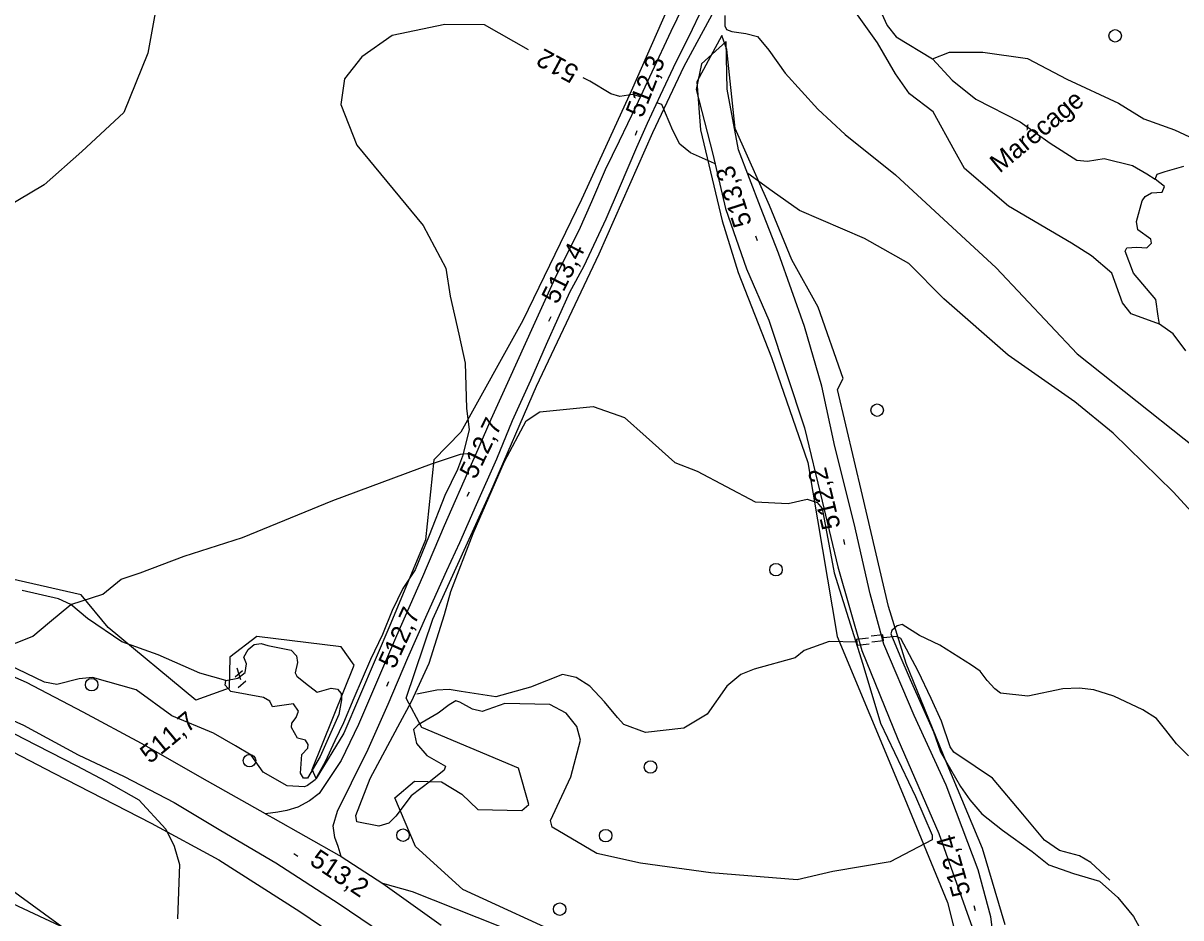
# Model space of a CAD drawing. Extents: x 347059 to 352153, y 6073752 to 6078601.
# Drawn here: x 349136.4 to 349414.6, y 6075948.3 to 6076163.4 of the extents above; entities that cross this region are included whole.
import ezdxf

# ---------------------------------------------------------------- set-up
doc = ezdxf.new("R2010")
doc.units = 0
for name, color, linetype in [('Level 1', 7, 'Continuous'), ('Level 19', 7, 'Continuous'), ('Level 2', 7, 'Continuous'), ('Level 21', 7, 'Continuous'), ('Level 22', 7, 'Continuous'), ('Level 26', 7, 'Continuous'), ('Level 3', 7, 'Continuous'), ('Level 36', 7, 'Continuous'), ('Level 37', 7, 'Continuous'), ('Level 4', 7, 'Continuous'), ('Level 44', 7, 'Continuous'), ('Level 7', 7, 'Continuous')]:
    doc.layers.add(name, color=color, linetype=linetype)

msp = doc.modelspace()

# ---------------------------------------------------------------- linework, layer by layer
at = {"layer": 'Level 1'}
for points in [[(349305.02, 6076165.23), (349305, 6076162.73), (349305.41, 6076161.87), (349306.72, 6076161.39), (349310.05, 6076160.92), (349312.85, 6076160.17)], [(349312.85, 6076160.17), (349315.56, 6076156.93), (349319.52, 6076151.42), (349327.38, 6076142.73), (349333.9, 6076136.65), (349346.01, 6076126.93), (349370.23, 6076104.59), (349389.67, 6076083.93), (349429.81, 6076052.02), (349436.05, 6076046.93)]]:
    msp.add_lwpolyline(points, dxfattribs=at)
at = {"layer": 'Level 19'}
for points in [[(349370.57, 6075935.79), (349368.94, 6075948.55), (349365.87, 6075959.81), (349358.21, 6075980.17), (349350.54, 6075996.92), (349343.25, 6076014.13), (349339.93, 6076026.23), (349336.06, 6076043.12), (349331.44, 6076061.63), (349328.34, 6076076.15), (349324.16, 6076090.51), (349317.9, 6076108.1), (349313.59, 6076119.2), (349308.28, 6076132.95), (349305.59, 6076147.53), (349305.34, 6076159.03), (349299.42, 6076153.66), (349298.11, 6076147.47), (349302.1, 6076131.88), (349305.17, 6076118.85), (349310.23, 6076104.32), (349315.58, 6076091.97), (349324.12, 6076066.08), (349328.41, 6076048.5), (349332.13, 6076032.68), (349337.93, 6076012.58), (349346.56, 6075991.24), (349356.47, 6075968.54), (349364.43, 6075946.03)], [(349255.95, 6075944.25), (349229.96, 6075954.53), (349222.77, 6075956.58)]]:
    msp.add_lwpolyline(points, dxfattribs=at)
at = {"layer": 'Level 2'}
for points in [[(349257.8, 6076157.01), (349247.23, 6076163.04), (349237.72, 6076163.08), (349225.01, 6076160.46), (349217.73, 6076155.31), (349213.56, 6076150.04), (349212.74, 6076143.81), (349216.52, 6076134.06), (349232.46, 6076114.78), (349237.91, 6076104.47), (349239.01, 6076097.74), (349241.05, 6076088.64), (349242.61, 6076081.62), (349242.94, 6076070.87), (349243.53, 6076065.66), (349241.96, 6076059.33)], [(349284.66, 6076145.66), (349282.89, 6076146.29), (349279.8, 6076145.75), (349277.63, 6076146.43), (349272.56, 6076149.43), (349270.93, 6076150.25)], [(349302.62, 6076129.67), (349302.53, 6076129.7), (349296.77, 6076132.19), (349294.22, 6076134.34), (349292.47, 6076137.61), (349289.84, 6076143.82), (349288.65, 6076144.24)], [(349429.29, 6076031.19), (349419.03, 6076043.95), (349412.75, 6076050.7), (349398.36, 6076064.84), (349389.11, 6076072.35), (349373.12, 6076083.61), (349357.65, 6076097.15), (349349.2, 6076105.6), (349338.6, 6076111.67), (349322.92, 6076118.37), (349316.41, 6076123.01), (349310.56, 6076127.22), (349310.48, 6076127.24)], [(349257.22, 6076067.83), (349260.53, 6076069.98), (349273.36, 6076071.2), (349280.92, 6076068.63), (349286.07, 6076063.91), (349292.98, 6076057.79), (349298.36, 6076055.67), (349312.3, 6076048.35), (349320.22, 6076047.88), (349324.76, 6076048.94), (349327.23, 6076048.14), (349328.41, 6076046.73), (349331.3, 6076031.27), (349338.2, 6076009.31), (349342.44, 6075995.12), (349350.8, 6075977.44), (349354.84, 6075968.18), (349354.82, 6075967.03), (349344.77, 6075961.76), (349330.92, 6075959.41), (349322.4, 6075957.44), (349301.61, 6075959.09), (349284.75, 6075961.44), (349274.21, 6075963.79), (349263.54, 6075970.09), (349263.11, 6075971.68), (349268.02, 6075982.21), (349270.31, 6075991.02), (349269.42, 6075994.33), (349266.88, 6075997.47), (349262.97, 6075999.63), (349252.16, 6075999.87), (349246.68, 6075997.87), (349244.38, 6075998.47)], [(349244.38, 6075998.47), (349241.3, 6076000.18), (349240.38, 6076000.47), (349238.77, 6075999.51), (349236.09, 6075997.5), (349231.27, 6075994.7), (349230.19, 6075993.58), (349230.86, 6075990.24), (349233.35, 6075987.35), (349237.87, 6075984.73), (349237.53, 6075983.78), (349234.3, 6075981.16), (349229.62, 6075977.66), (349225.97, 6075972.75), (349224.26, 6075971.1), (349221.86, 6075970.38), (349216.58, 6075971.39), (349216.35, 6075972.93), (349219.79, 6075981.79), (349226.43, 6075994.2), (349229.72, 6076000.35), (349233.97, 6076009.51), (349237.59, 6076021.21), (349239.12, 6076026.77), (349244.55, 6076040.73), (349252.01, 6076058.02), (349257.22, 6076067.83)], [(349241.96, 6076059.33), (349240.77, 6076056.11), (349237.69, 6076049.88), (349233.97, 6076040.23), (349230.54, 6076032), (349227.63, 6076027.5), (349225.07, 6076022.23), (349222.69, 6076016.44), (349219.84, 6076010.4), (349219.84, 6076010.4), (349215.86, 6076001.1), (349213.39, 6075995.2), (349211.29, 6075990.83), (349208.91, 6075985.84), (349206.51, 6075981.5), (349204.71, 6075980.15), (349203.95, 6075979.8), (349199.78, 6075980.01), (349194.06, 6075983.36), (349191.2, 6075987.42), (349187.43, 6075989.69), (349182.08, 6075992.67), (349172.1, 6075996.9), (349163.53, 6076003.12), (349153.06, 6076006.11), (349149.83, 6076005.75), (349144.42, 6076004.4), (349141.52, 6076004.99), (349130.57, 6076010.2)], [(349351.79, 6076016.17), (349347.64, 6076018.86), (349346.45, 6076018.54), (349345.17, 6076017.37), (349344.88, 6076016.6), (349347.04, 6076011.36), (349349.52, 6076005.58), (349355.17, 6075993), (349356.8, 6075988.25), (349361.64, 6075979.9), (349363.86, 6075976.69), (349366.78, 6075973.27), (349371.76, 6075969.41), (349378.86, 6075964.24), (349382.89, 6075961.06), (349388.77, 6075959), (349395.03, 6075957.12), (349399.42, 6075953.18), (349403.25, 6075948.64), (349406.31, 6075942.95)], [(349416.44, 6075987.22), (349413.54, 6075990.14), (349410.97, 6075993.45), (349408.71, 6075996.23), (349405.44, 6075998.31), (349398.45, 6076001.58), (349393.68, 6076003.09), (349390.17, 6076003.53), (349386.25, 6076003.36), (349377.82, 6076001.62), (349371.23, 6076002.31), (349369.88, 6076003.32), (349368.05, 6076005.4), (349366.38, 6076007.6), (349364.28, 6076009.06), (349356.71, 6076013.84), (349351.79, 6076016.17)], [(349122.22, 6075998.85), (349136.41, 6075991.38), (349149.3, 6075984.85), (349156.21, 6075981.15), (349164.17, 6075976.66), (349170.69, 6075969.64), (349172.66, 6075965.57), (349173.93, 6075961.15), (349173.47, 6075948.09)]]:
    msp.add_lwpolyline(points, dxfattribs=at)
at = {"layer": 'Level 21'}
for points in [[(349296.43, 6076170.52), (349292.02, 6076161.37), (349287.43, 6076151.64), (349283.59, 6076143.35), (349279.63, 6076135.03), (349276.25, 6076128.18), (349272.92, 6076120.47), (349269.91, 6076113.55), (349264.51, 6076102.93), (349258.91, 6076090.56), (349253.19, 6076077.79), (349248.78, 6076068.13), (349245.05, 6076059.59), (349244.05, 6076057.31), (349237.53, 6076042.51), (349232.34, 6076030.26), (349226.12, 6076016.1), (349221.06, 6076004.32), (349216.94, 6075994.75), (349212.82, 6075986.09), (349207.47, 6075978.19), (349205.22, 6075976.47), (349202.37, 6075974.93), (349199.72, 6075974.14), (349197.59, 6075973.72), (349194.58, 6075973.32)], [(349212.81, 6075963.01), (349212.11, 6075965.47), (349211.28, 6075967.63), (349210.88, 6075970.45), (349211.94, 6075973.95), (349215.27, 6075980.77), (349219.26, 6075988.87), (349224.07, 6075999.69), (349228.78, 6076010.8), (349233.44, 6076021.34), (349238.17, 6076031.8), (349241.29, 6076038.51), (349245.29, 6076047.68), (349250.23, 6076058.69), (349253.99, 6076067.88), (349258.4, 6076077.54), (349262.15, 6076086.19), (349267.76, 6076098.72), (349271.17, 6076105.08), (349276.47, 6076116.37), (349279.65, 6076123.8), (349283.87, 6076133.61), (349286.41, 6076139.4), (349289.53, 6076146.12), (349293.3, 6076154.13), (349296.4, 6076160.24), (349299.71, 6076167.19)], [(349194.58, 6075973.32), (349180.66, 6075981.15), (349164.82, 6075990.24), (349150.8, 6075997.78), (349137.19, 6076004.9), (349127.02, 6076009.26)], [(349126.47, 6075999.15), (349136.46, 6075994.64), (349149.61, 6075987.51), (349160.65, 6075982.3), (349172.62, 6075976.05), (349183.84, 6075969.26), (349197.1, 6075961.55), (349212.34, 6075951.65), (349225.19, 6075942.91)], [(349194.58, 6075973.32), (349196.36, 6075972.32), (349212.21, 6075963.39), (349212.81, 6075963.01), (349222.77, 6075956.58), (349236.8, 6075946.51)]]:
    msp.add_lwpolyline(points, dxfattribs=at)
at = {"layer": 'Level 22'}
msp.add_lwpolyline([(349124.39, 6076010.3), (349124.98, 6076013.19), (349127.47, 6076015.25), (349134.52, 6076014.37), (349138.69, 6076016.04), (349142.69, 6076019.36), (349147.83, 6076023.6), (349155.52, 6076026.09), (349159.88, 6076029.71), (349164.45, 6076031.26), (349175.07, 6076035.29), (349189.1, 6076039.75), (349210.76, 6076048.6), (349234.54, 6076057.42), (349241.48, 6076059.74), (349243.14, 6076059.92), (349245.05, 6076059.59)], dxfattribs=at)
at = {"layer": 'Level 26'}
for p, q in [((349336.63, 6076015.33), (349339.49, 6076015.65)), ((349336.63, 6076015.33), (349336.81, 6076013.87)), ((349343.01, 6076016.35), (349340.14, 6076016.03)), ((349343.17, 6076014.89), (349343.01, 6076016.35)), ((349336.81, 6076013.87), (349339.66, 6076014.21)), ((349343.17, 6076014.89), (349340.31, 6076014.59))]:
    msp.add_line(p, q, dxfattribs=at)
at = {"layer": 'Level 3'}
for p, q in [((349283.53, 6076136.44), (349283.97, 6076137.56)), ((349312.84, 6076111.04), (349312.47, 6076112.18)), ((349262.72, 6076091.79), (349263.26, 6076092.86)), ((349243.11, 6076049.67), (349243.64, 6076050.75)), ((349333.86, 6076038.1), (349333.57, 6076039.27)), ((349187.29, 6076006.24), (349189.1, 6076007.73)), ((349187.75, 6076008.37), (349188.58, 6076005.62)), ((349188.01, 6076003.72), (349189.86, 6076005.25)), ((349223.78, 6076004.04), (349224.28, 6076005.13)), ((349201.38, 6075963.77), (349202.38, 6075963.1)), ((349365.26, 6075949.99), (349364.93, 6075951.15))]:
    msp.add_line(p, q, dxfattribs=at)
at = {"layer": 'Level 36'}
for centre in [(349398.81, 6076160.37), (349341.6, 6076070.35), (349317.28, 6076032), (349152.83, 6076004.36), (349190.77, 6075986.09), (349287.13, 6075984.56), (349227.67, 6075968.16), (349276.37, 6075968.06), (349265.31, 6075950.37)]:
    msp.add_circle(centre, 1.5, dxfattribs=at)
at = {"layer": 'Level 37'}
msp.add_lwpolyline([(349105.83, 6075964.84), (349145.26, 6075946.36), (349226.4, 6075910.98), (349265.54, 6075890.33), (349312.79, 6075813.11), (349333.88, 6075779.73), (349343.28, 6075763.05)], dxfattribs=at)
at = {"layer": 'Level 4'}
for points in [[(349318.16, 6076192.02), (349322.53, 6076191.3), (349327.23, 6076189.19), (349333, 6076183.47), (349336.12, 6076178.56), (349339.38, 6076173.22), (349342.69, 6076165.83), (349344.02, 6076162.88), (349346.19, 6076160.1), (349354.89, 6076154.85), (349359.64, 6076149.7), (349365.31, 6076145.17), (349375.96, 6076139.65), (349383.19, 6076134.53), (349389.61, 6076130.46), (349392.18, 6076130.19), (349396.2, 6076130.89), (349402.96, 6076129.22), (349406.43, 6076127.14), (349408.44, 6076125.92)], [(349415.78, 6076084.61), (349412.73, 6076088.71), (349409.44, 6076091.02), (349409.17, 6076092.97), (349408.59, 6076097), (349403.2, 6076103.28), (349401.21, 6076108.55), (349401.62, 6076109.42), (349404.02, 6076109.53), (349406.43, 6076109.35), (349407.52, 6076110.48), (349407.36, 6076111.48), (349404.28, 6076113.73), (349403.97, 6076115.73), (349405.28, 6076120.66), (349406.04, 6076121.74), (349407.56, 6076122.63), (349410.09, 6076122.77), (349410.67, 6076124.16), (349408.44, 6076125.92), (349408.88, 6076127.11), (349410.83, 6076127.76), (349415.35, 6076129.03)], [(349185.11, 6076005.39), (349178.79, 6076007.11), (349168.82, 6076011.5), (349160.05, 6076014.63), (349151.83, 6076020.25), (349147.83, 6076023.6), (349144.85, 6076025.01), (349136.13, 6076026.99)], [(349397.55, 6075957.36), (349392.97, 6075961.59), (349390.27, 6075963.21), (349385.42, 6075964.51), (349381.86, 6075966.97), (349376.64, 6075973.22), (349369.34, 6075981.87), (349365.16, 6075984.71), (349360.05, 6075988.13), (349359.14, 6075989.4), (349357.04, 6075995.61), (349354.62, 6076001.03), (349351.45, 6076007.63), (349347.32, 6076015.46), (349346.22, 6076015.97), (349343.11, 6076015.64)], [(349189.4, 6076010.98), (349190.48, 6076012.85), (349191.85, 6076013.99), (349193.6, 6076014.24), (349195.2, 6076013.77), (349200.76, 6076012.69), (349202.02, 6076011.27), (349202.29, 6076009.69), (349201.77, 6076007.24), (349202.15, 6076006.43), (349204.21, 6076004.76), (349207.01, 6076002.59), (349210.42, 6076003.55), (349211.95, 6076003.24), (349212.8, 6076002.22), (349212.87, 6076000.7), (349212.26, 6075997.2), (349207.76, 6075987.08), (349204.7, 6075981.91), (349203.75, 6075981.87), (349202.99, 6075983.05), (349203.37, 6075987.56), (349204.78, 6075989.11), (349204.9, 6075989.96), (349204.18, 6075991.01), (349202.26, 6075991.51), (349200.89, 6075994.05), (349200.91, 6075995.11), (349201.97, 6075996.45), (349202.56, 6075997.99), (349201.33, 6075999.74), (349196.3, 6075999.01), (349195.61, 6076000.39), (349194.09, 6076001.3), (349186.3, 6076002.7), (349184.88, 6076004.23), (349185.11, 6076005.39), (349187.96, 6076005.95), (349189.72, 6076007.27), (349190.07, 6076009.36), (349189.4, 6076010.98)], [(349336.69, 6076014.58), (349330.05, 6076014.77), (349324.06, 6076012.57), (349321.93, 6076010.8), (349312.03, 6076008.05), (349308.87, 6076006.78), (349305.49, 6076003.97), (349300.73, 6075997.24), (349295.17, 6075993.89), (349285.96, 6075992.84), (349280.76, 6075994.75), (349279.19, 6075996.45), (349276.09, 6076000.25), (349272.53, 6076003.97), (349269.24, 6076006.12), (349265.98, 6076006.78), (349258.27, 6076003.75), (349249.93, 6076001.4), (349241.6, 6076002.73), (349238.77, 6076003.23), (349235.76, 6076003.05), (349230.99, 6076002.09)]]:
    msp.add_lwpolyline(points, dxfattribs=at)
at = {"layer": 'Level 44'}
for points in [[(349268.57, 6075942.91), (349242.02, 6075955.09), (349230.64, 6075965.48), (349225.72, 6075977.13), (349230.38, 6075981.14), (349236.9, 6075981.03), (349241.81, 6075978.04), (349245.64, 6075974.34), (349256.2, 6075974.12), (349257.89, 6075975.52), (349255.41, 6075984.26), (349232.21, 6075994.06), (349228.43, 6076001.11), (349234.84, 6076020.07), (349248.73, 6076050.8), (349259.75, 6076076.15), (349274.8, 6076107.96), (349287.71, 6076137.1), (349295.24, 6076153.1), (349304.53, 6076170.27)], [(349291.25, 6076166.83), (349282.46, 6076147.08), (349270.56, 6076121.02), (349256.44, 6076091.93), (349241.53, 6076065.05), (349235.03, 6076058.45), (349233.09, 6076039.16), (349224.7, 6076019.16), (349213.42, 6075992.71), (349206.76, 6075981.78), (349205.82, 6075984), (349215.9, 6076009.01), (349212.79, 6076013.47), (349192.53, 6076015.96), (349186.01, 6076010.99), (349185.89, 6076003.49), (349177.86, 6076000.6), (349156.78, 6076018.13), (349150.29, 6076025.92), (349118.22, 6076033.24)], [(349372.4, 6075946.59), (349366.96, 6075964.97), (349358.42, 6075985.28), (349348.6, 6076009.42), (349344.37, 6076023.17), (349338.08, 6076049.84), (349332.07, 6076075.32), (349333.46, 6076077.98), (349327.41, 6076095.13), (349321.07, 6076106.5), (349315.71, 6076119.58), (349307.49, 6076138.07), (349305.46, 6076157.07), (349304.29, 6076160.45), (349298.25, 6076149.28), (349299.16, 6076137.74), (349304.37, 6076115.85), (349308.23, 6076103.49), (349316.18, 6076083), (349324.93, 6076057.77), (349331.98, 6076015.93), (349347.7, 6075978.3), (349358.54, 6075952.01), (349362.11, 6075937.71)], [(349125.97, 6075992.29), (349143.72, 6075983.07), (349167.11, 6075971.04), (349183.43, 6075962.28), (349202.85, 6075949.8), (349215.27, 6075941.38)], [(349134.54, 6075873.8), (349140.24, 6075874.18), (349155.53, 6075874.58), (349159.66, 6075872.32), (349165.31, 6075858.86), (349173.54, 6075850.25), (349187.59, 6075847.81), (349205.25, 6075841.94), (349210.27, 6075849.26), (349210.44, 6075855.55), (349204.45, 6075866.17), (349196.17, 6075872.49), (349182.76, 6075881.74), (349169.41, 6075893.44), (349159.47, 6075904.83), (349150.05, 6075915.59), (349146.1, 6075931.51), (349149.49, 6075943.32), (349130.43, 6075957.17)]]:
    msp.add_lwpolyline(points, dxfattribs=at)
at = {"layer": 'Level 7'}
for points in [[(349126.55, 6076252.65), (349142.87, 6076231.3), (349158.31, 6076211.91), (349163.02, 6076195.44), (349168.75, 6076169.47), (349166.3, 6076156.18), (349160.56, 6076141.96), (349150.5, 6076132.55), (349141.4, 6076124.53), (349116.85, 6076109.96)], [(349409.44, 6076091.03), (349402.67, 6076093.53), (349400.61, 6076096.17), (349397.97, 6076103.31), (349393.16, 6076107.44), (349388.33, 6076110.5), (349373.18, 6076119.42), (349362.57, 6076128.5), (349360.31, 6076132.65), (349355.08, 6076142.06), (349349.35, 6076146.4), (349346.05, 6076151.25), (349341.72, 6076158.69), (349335.66, 6076167.11), (349330.39, 6076174.68), (349326.63, 6076182.07), (349322.84, 6076187.33), (349322.53, 6076191.3)], [(349354.89, 6076154.85), (349358.98, 6076156.45), (349366.97, 6076156.47), (349377.77, 6076154.92), (349387.2, 6076149.97), (349399.59, 6076144.17), (349405.67, 6076140.42), (349413.04, 6076137.75), (349420.16, 6076134.48), (349428.15, 6076133.14), (349433.59, 6076131.42), (349436.44, 6076129.73), (349440, 6076128.55), (349443.66, 6076128.5), (349446.92, 6076127.6), (349449.15, 6076124.84)]]:
    msp.add_lwpolyline(points, dxfattribs=at)

# ---------------------------------------------------------------- texts
at = {"layer": 'Level 2'}
msp.add_text('512', height=4.5, rotation=151.6901, dxfattribs=at).set_placement((349270.25, 6076152.71))
at = {"layer": 'Level 3'}
for s, rotation, p in [('512,3', 68.4122, (349285.18, 6076140.44)), ('513,3', 107.8402, (349311.56, 6076115.18)), ('513,4', 63.2161, (349264.72, 6076095.62)), ('512,7', 63.9658, (349245.05, 6076053.53)), ('512,2', 103.9005, (349332.87, 6076042.3)), ('512,7', 65.4797, (349225.62, 6076007.94)), ('  511,7', 39.57, (349164.24, 6075983.07)), ('512,4', 105.8845, (349364.13, 6075954.16)), ('513,2', 326.4038, (349204.95, 6075961.34))]:
    msp.add_text(s, height=4.5, rotation=rotation, dxfattribs=at).set_placement(p)
at = {"layer": 'Level 7'}
msp.add_text('Marécage', height=4.5, rotation=39.568, dxfattribs=at).set_placement((349371.05, 6076127.2))

doc.saveas('drawing.dxf')
